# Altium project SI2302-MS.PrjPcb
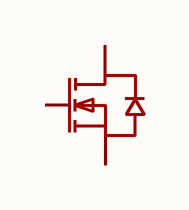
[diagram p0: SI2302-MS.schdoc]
1 sheet, 1 parts. Net scope: global (net labels, ports and power ports of the same name join across sheets).

## Sheet SI2302-MS.schdoc
size 127 x 101 mm

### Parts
Q?  si2302-ms  [SOT-23-3_L2.9-W1.3-P1.90-LS2.4-BR]  (value not drawn)

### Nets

Not connected (* = marked no-connect by the designer): Q? 1(G) 2(S) 3(D)

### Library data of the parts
Q? = si2302-ms: 数量:1个N沟道;漏源电压(Vdss):20V;连续漏极电流(Id):2.8A;导通电阻(RDS(on)):60mΩ@4.5V;耗散功率(Pd):1.56W;阈值电压(Vgs(th)):1V;; Manufacturer: MSKSEMI(美森科); AddInBom: yes; ModelId: c62791f0466c4ae2a892c056b845b0ca; ModelName: SOT-23-3P_L2.9-W1.3-H1.0-LS2.4-P0.95; ModelTransform: 98.425,114.173,0,180,0,0,0.0005,-0.0005,0; Number: 1个N沟道; Drain to Source Voltage: 20V; Current - Continuous Drain(Id): 2.8A; Pd - Power Dissipation: 1.56W; Gate Threshold Voltage (Vgs(th)): 1V; Gate Charge(Qg): 7.2nC@4.5V; Input Capacitance(Ciss): 360pF; Reverse Transfer Capacitance (Crss@Vds): 52pF; Output Capacitance(Coss): 64pF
